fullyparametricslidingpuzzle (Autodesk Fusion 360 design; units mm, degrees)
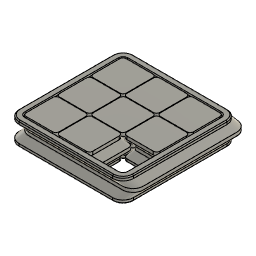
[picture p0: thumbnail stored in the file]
parameter "clear" = 0.3
parameter "length" = 20
parameter "fillet" = 2
parameter "chamfer" = 0.6
parameter "extrude" = 2
parameter "z_offset" = 4
parameter "xy_offset" = 3
sketch "Sketch1" plane through (0, 0, 0) normal (0, 0, 1) x axis (1, 0, 0)
  line L1 (28.3, -30.6) -> (-28.3, -30.6)
  line L2 (30.6, 28.3) -> (30.6, -28.3)
  line L3 (-28.3, 30.6) -> (28.3, 30.6)
  line L4 (-30.6, -28.3) -> (-30.6, 28.3)
  line L5 (30.6, 30.6) -> (-30.6, -30.6)
  line L6 (-30.6, 30.6) -> (30.6, -30.6)
  line L7 (-12.3, -30.3) -> (-28.3, -30.3)
  line L8 (-10.3, -12.3) -> (-10.3, -28.3)
  line L9 (-28.3, -10.3) -> (-12.3, -10.3)
  line L10 (-30.3, -28.3) -> (-30.3, -12.3)
  line L11 (-34.6, -28.3) -> (-34.6, 28.3)
  line L12 (28.3, -34.6) -> (-28.3, -34.6)
  line L13 (34.6, 28.3) -> (34.6, -28.3)
  line L14 (-28.3, 34.6) -> (28.3, 34.6)
  arc A1 centre (-28.3, -28.3) radius 2 clockwise from (-28.3, -30.3) to (-30.3, -28.3)
  arc A2 centre (-28.3, -12.3) radius 2 clockwise from (-30.3, -12.3) to (-28.3, -10.3)
  arc A3 centre (-12.3, -12.3) radius 2 clockwise from (-12.3, -10.3) to (-10.3, -12.3)
  arc A4 centre (-12.3, -28.3) radius 2 clockwise from (-10.3, -28.3) to (-12.3, -30.3)
  arc A5 centre (-28.3, 28.3) radius 2.3 clockwise from (-30.6, 28.3) to (-28.3, 30.6)
  arc A6 centre (28.3, 28.3) radius 2.3 clockwise from (28.3, 30.6) to (30.6, 28.3)
  arc A7 centre (28.3, -28.3) radius 2.3 clockwise from (30.6, -28.3) to (28.3, -30.6)
  arc A8 centre (-28.3, -28.3) radius 2.3 clockwise from (-28.3, -30.6) to (-30.6, -28.3)
  arc A9 centre (-28.3, -28.3) radius 6.3 clockwise from (-28.3, -34.6) to (-34.6, -28.3)
  arc A10 centre (28.3, -28.3) radius 6.3 clockwise from (34.6, -28.3) to (28.3, -34.6)
  arc A11 centre (28.3, 28.3) radius 6.3 clockwise from (28.3, 34.6) to (34.6, 28.3)
  arc A12 centre (-28.3, 28.3) radius 6.3 clockwise from (-34.6, 28.3) to (-28.3, 34.6)
  point P6 (0, 0)
  point P1 (0, 0)
  point P7 (-30.3, -30.3)
  point P9 (-30.3, -10.3)
  point P8 (-10.3, -30.3)
  point P5 (-30.6, 30.6)
  point P4 (30.6, 30.6)
  point P3 (30.6, -30.6)
  point P2 (-30.6, -30.6)
  horizontal L1
  perpendicular L1 L2
  parallel L1 L3
  parallel L2 L4
  coincident L5 P6
  coincident L6 P6
  coincident P1 P6
  horizontal L7
  vertical L8
  horizontal L9
  vertical L10
  coincident P7 L10
  coincident P7 L7
  tangent L10 A1
  tangent L7 A1
  coincident P9 L9
  coincident P9 L10
  tangent L9 A2
  tangent L10 A2
  equal A1 A2
  tangent L9 A3
  tangent L8 A3
  coincident P8 L8
  coincident P8 L7
  tangent L8 A4
  tangent L7 A4
  coincident P5 L3
  coincident P5 L4
  tangent L3 A5
  tangent L4 A5
  coincident P4 L3
  coincident P4 L2
  tangent L3 A6
  tangent L2 A6
  coincident P3 L2
  coincident P3 L1
  tangent L2 A7
  tangent L1 A7
  coincident P2 L4
  coincident P2 L1
  tangent L4 A8
  tangent L1 A8
  equal A7 A8
  dimension "d6" distance P7 P8 = 20 (= "length")
  dimension "d7" distance P7 P9 = 20 (= "length")
  dimension "d8" distance L4 L10 = 0.3 (= "clear")
  dimension "d9" distance L1 L7 = 0.3 (= "clear")
  dimension "d10" distance P2 P3 = 61.2 (= "x_number * length + ( x_number + 1 ) * clear")
  dimension "d11" distance P2 P5 = 61.2 (= "y_number * length + ( y_number + 1 ) * clear")
  dimension "d12" radius A1 = 2 (= "fillet")
  dimension "d13" radius A3 = 2 (= "fillet")
  dimension "d14" radius A4 = 2 (= "fillet")
  dimension "d15" radius A5 = 2.3 (= "fillet + 0.3 mm")
  dimension "d16" radius A6 = 2.3 (= "fillet + 0.3 mm")
  dimension "d17" radius A7 = 2.3 (= "fillet + 0.3 mm")
  dimension "d18" = 4
extrude "Extrude2" new body sketch "Sketch1" profile of L1 L2 L3 L4 L7 L8 L9 L10 A1 A2 A3 A4 A5 A6 A7 A8 L12 L11 L13 A9 L14 A10 A11 A12 along normal blind 2 (= "extrude")
work_plane "WorkPlane1" AlongDistance 4 (= "z_offset")
sketch "Sketch4" plane through (0, 0, 6) normal (0, 0, 1) x axis (1, 0, 0)
  line L1 (-25.3, -7.3) -> (-9.3, -7.3)
  line L2 (-25.3, 33.6) -> (31.3, 33.6)
  line L3 (-27.6, -25.3) -> (-27.6, 31.3)
  line L4 (33.6, 31.3) -> (33.6, -25.3)
  line L5 (33.6, 33.6) -> (-27.6, -27.6)
  line L6 (31.3, -27.6) -> (-25.3, -27.6)
  line L7 (-9.3, -27.3) -> (-25.3, -27.3)
  line L8 (31.3, -31.6) -> (-25.3, -31.6)
  line L9 (-27.6, 33.6) -> (33.6, -27.6)
  line L10 (-25.3, 37.6) -> (31.3, 37.6)
  line L11 (-7.3, -9.3) -> (-7.3, -25.3)
  line L12 (-31.6, -25.3) -> (-31.6, 31.3)
  line L13 (37.6, 31.3) -> (37.6, -25.3)
  line L14 (-27.3, -25.3) -> (-27.3, -9.3)
  line L15 (-10.3, -12.3) -> (-10.3, -28.3)
  line L16 (-28.3, -10.3) -> (-12.3, -10.3)
  line L17 (-30.3, -28.3) -> (-30.3, -12.3)
  line L18 (-12.3, -30.3) -> (-28.3, -30.3)
  line L19 (-10.8858, -29.7142) -> (-29.7142, -10.8858)
  line L20 (-7.8858, -26.7142) -> (-26.7142, -7.8858)
  arc A1 centre (31.3, 31.3) radius 2.3 clockwise from (31.3, 33.6) to (33.6, 31.3)
  arc A2 centre (-25.3, -25.3) radius 2 clockwise from (-25.3, -27.3) to (-27.3, -25.3)
  arc A3 centre (31.3, 31.3) radius 6.3 clockwise from (31.3, 37.6) to (37.6, 31.3)
  arc A4 centre (-25.3, 31.3) radius 6.3 clockwise from (-31.6, 31.3) to (-25.3, 37.6)
  arc A5 centre (-25.3, -25.3) radius 6.3 clockwise from (-25.3, -31.6) to (-31.6, -25.3)
  arc A6 centre (31.3, -25.3) radius 6.3 clockwise from (37.6, -25.3) to (31.3, -31.6)
  arc A7 centre (-9.3, -9.3) radius 2 clockwise from (-9.3, -7.3) to (-7.3, -9.3)
  arc A8 centre (31.3, -25.3) radius 2.3 clockwise from (33.6, -25.3) to (31.3, -27.6)
  arc A9 centre (-25.3, -25.3) radius 2.3 clockwise from (-25.3, -27.6) to (-27.6, -25.3)
  arc A10 centre (-25.3, -9.3) radius 2 clockwise from (-27.3, -9.3) to (-25.3, -7.3)
  arc A11 centre (-9.3, -25.3) radius 2 clockwise from (-7.3, -25.3) to (-9.3, -27.3)
  arc A12 centre (-25.3, 31.3) radius 2.3 clockwise from (-27.6, 31.3) to (-25.3, 33.6)
  arc A13 centre (-12.3, -28.3) radius 2 clockwise from (-10.3, -28.3) to (-12.3, -30.3)
  arc A14 centre (-12.3, -12.3) radius 2 clockwise from (-12.3, -10.3) to (-10.3, -12.3)
  arc A15 centre (-28.3, -12.3) radius 2 clockwise from (-30.3, -12.3) to (-28.3, -10.3)
  arc A16 centre (-28.3, -28.3) radius 2 clockwise from (-28.3, -30.3) to (-30.3, -28.3)
  point P28 (3, 3)
  point P9 (3, 3)
  point P36 (-27.3, -27.3)
  point P37 (-27.3, -7.3)
  point P38 (-7.3, -27.3)
  point P32 (-27.6, 33.6)
  point P6 (33.6, 33.6)
  point P8 (33.6, -27.6)
  point P7 (-27.6, -27.6)
  point P59 (-29.7142, -10.8858)
  point P60 (-10.8858, -29.7142)
  point P61 (-20.3, -20.3)
  point P62 (-26.7142, -7.8858)
  point P63 (-7.8858, -26.7142)
  point P64 (-17.3, -17.3)
  horizontal L6
  perpendicular L4 L6
  parallel L2 L6
  parallel L3 L4
  coincident P28 L5
  coincident P28 L9
  coincident P9 P28
  horizontal L7
  vertical L11
  horizontal L1
  vertical L14
  coincident P36 L14
  coincident P36 L7
  tangent A2 L14
  tangent A2 L7
  coincident P37 L1
  coincident P37 L14
  tangent L1 A10
  tangent A10 L14
  equal A2 A10
  tangent L1 A7
  tangent A7 L11
  coincident P38 L11
  coincident P38 L7
  tangent A11 L11
  tangent L7 A11
  coincident P32 L2
  coincident P32 L3
  tangent L2 A12
  tangent L3 A12
  coincident P6 L2
  coincident P6 L4
  tangent A1 L2
  tangent A1 L4
  coincident P8 L4
  coincident P8 L6
  tangent L4 A8
  tangent L6 A8
  coincident P7 L3
  coincident P7 L6
  tangent L3 A9
  tangent L6 A9
  equal A8 A9
  midpoint A15 P59
  midpoint A13 P60
  midpoint L19 P61
  midpoint A10 P62
  midpoint A11 P63
  midpoint L20 P64
  dimension "d27" = 4
  dimension "d28" distance P36 P38 = 20 (= "length")
  dimension "d29" distance P36 P37 = 20 (= "length")
  dimension "d30" distance L3 L14 = 0.3 (= "clear")
  dimension "d31" distance L6 L7 = 0.3 (= "clear")
  dimension "d32" distance P7 P8 = 61.2 (= "x_number * length + ( x_number + 1 ) * clear")
  dimension "d33" distance P7 P32 = 61.2 (= "y_number * length + ( y_number + 1 ) * clear")
  dimension "d34" radius A2 = 2 (= "fillet")
  dimension "d35" radius A7 = 2 (= "fillet")
  dimension "d36" radius A11 = 2 (= "fillet")
  dimension "d37" radius A12 = 2.3 (= "fillet + 0.3 mm")
  dimension "d38" radius A1 = 2.3 (= "fillet + 0.3 mm")
  dimension "d39" radius A8 = 2.3 (= "fillet + 0.3 mm")
  dimension "d50" distance P61 P64 = 3 (= "xy_offset")
  dimension "d51" distance P61 P64 = 3 (= "xy_offset")
sketch "Sketch5" plane through (0, 0, 2) normal (0, 0, 1) x axis (-1, 0, 0)
  line L1 (30.6, -28.3) -> (30.6, 28.3)
  line L2 (-28.3, -30.6) -> (28.3, -30.6)
  line L3 (-30.6, 28.3) -> (-30.6, -28.3)
  line L4 (28.3, 30.6) -> (-28.3, 30.6)
  line L5 (34.6, 28.3) -> (34.6, -28.3)
  line L6 (-28.3, 34.6) -> (28.3, 34.6)
  line L7 (-34.6, -28.3) -> (-34.6, 28.3)
  line L8 (28.3, -34.6) -> (-28.3, -34.6)
  line L9 (10.3, 12.3) -> (10.3, 28.3)
  line L10 (28.3, 10.3) -> (12.3, 10.3)
  line L11 (30.3, 28.3) -> (30.3, 12.3)
  line L12 (12.3, 30.3) -> (28.3, 30.3)
  line L13 (28.3, 30.3) -> (12.3, 30.3)
  line L14 (30.3, 12.3) -> (30.3, 28.3)
  line L15 (12.3, 10.3) -> (28.3, 10.3)
  line L16 (10.3, 28.3) -> (10.3, 12.3)
  arc A1 centre (28.3, 28.3) radius 2.3 clockwise from (28.3, 30.6) to (30.6, 28.3)
  arc A2 centre (28.3, -28.3) radius 2.3 clockwise from (30.6, -28.3) to (28.3, -30.6)
  arc A3 centre (-28.3, -28.3) radius 2.3 clockwise from (-28.3, -30.6) to (-30.6, -28.3)
  arc A4 centre (-28.3, 28.3) radius 2.3 clockwise from (-30.6, 28.3) to (-28.3, 30.6)
  arc A5 centre (28.3, -28.3) radius 6.3 clockwise from (34.6, -28.3) to (28.3, -34.6)
  arc A6 centre (28.3, 28.3) radius 6.3 clockwise from (28.3, 34.6) to (34.6, 28.3)
  arc A7 centre (-28.3, 28.3) radius 6.3 clockwise from (-34.6, 28.3) to (-28.3, 34.6)
  arc A8 centre (-28.3, -28.3) radius 6.3 clockwise from (-28.3, -34.6) to (-34.6, -28.3)
  arc A9 centre (12.3, 28.3) radius 2 clockwise from (10.3, 28.3) to (12.3, 30.3)
  arc A10 centre (12.3, 12.3) radius 2 clockwise from (12.3, 10.3) to (10.3, 12.3)
  arc A11 centre (28.3, 12.3) radius 2 clockwise from (30.3, 12.3) to (28.3, 10.3)
  arc A12 centre (28.3, 28.3) radius 2 clockwise from (28.3, 30.3) to (30.3, 28.3)
  arc A13 centre (12.3, 28.3) radius 2 clockwise from (10.3, 28.3) to (12.3, 30.3)
  arc A14 centre (28.3, 28.3) radius 2 clockwise from (28.3, 30.3) to (30.3, 28.3)
  arc A15 centre (28.3, 12.3) radius 2 clockwise from (30.3, 12.3) to (28.3, 10.3)
  arc A16 centre (12.3, 12.3) radius 2 clockwise from (12.3, 10.3) to (10.3, 12.3)
loft "Loft1" sketch "Sketch5" + "Sketch4"
loft "Loft2" sketch "Sketch4" + "Sketch5"
loft "Loft3" sketch "Sketch4"
extrude "Extrude3" add of existing geometry blind 1 (= "extrude / 2")
mirror "Mirror1" mirrorStitchTolerance 0.1
rectangular_pattern "R-Pattern1" uSpaceDistance 40.6 (= "x_number * length + ( x_number + 1 ) * clear - length - 2 * clear") vSpaceDistance -40.6 (= "-( y_number * length + ( y_number + 1 ) * clear - length - 2 * clear )")
chamfer "Chamfer3" sketch "Sketch4" distance 0.6 (= "chamfer")
chamfer "Chamfer4" sketch "Sketch4" distance 0.6 (= "chamfer")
